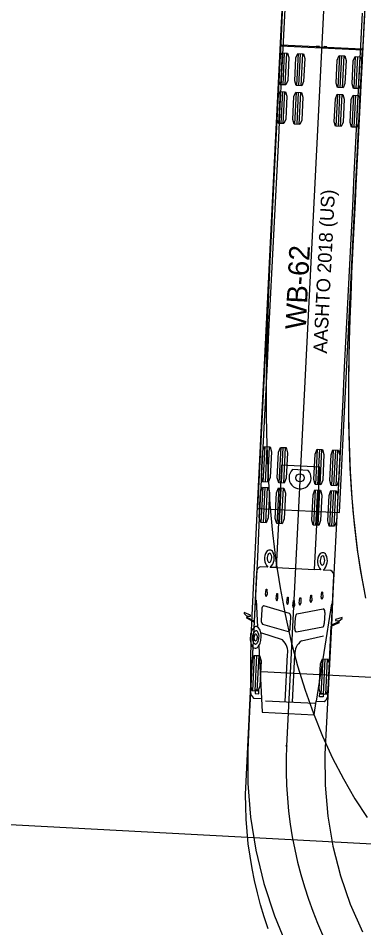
# Model space of a CAD drawing. Extents: x 260275 to 261282, y 610916 to 614143.
# Drawn here: x 260983.2 to 261018.9, y 611607.9 to 611701.9 of the extents above; entities that cross this region are included whole.
import ezdxf

# ---------------------------------------------------------------- set-up
doc = ezdxf.new("R2010")
doc.units = 0
doc.layers.add('DR_P_Ditch', color=7, linetype='Continuous')
doc.layers.add('UT_X_Water_Cells', color=7, linetype='Continuous')

msp = doc.modelspace()

# ---------------------------------------------------------------- linework, layer by layer
at = {"layer": 'DR_P_Ditch'}
msp.add_line((260830.144, 611626.697), (261021.455, 611616.54), dxfattribs=at)
at = {"layer": 'UT_X_Water_Cells'}
for p, q in [((261031.95, 612045.486), (261010.925, 611626.741)), ((261010.3, 611699.055), (261018.79, 611698.629)), ((261010.328, 611695.04), (261010.494, 611698.335)), ((261010.557, 611695.028), (261010.722, 611698.324)), ((261010.786, 611695.017), (261010.951, 611698.312)), ((261011.976, 611694.957), (261012.142, 611698.253)), ((261012.205, 611694.945), (261012.37, 611698.241)), ((261012.434, 611694.934), (261012.599, 611698.23)), ((261014.018, 611698.939), (261014.283, 611698.925)), ((261014.808, 611698.899), (261014.285, 611698.925)), ((261014.548, 611698.912), (261014.545, 611698.842)), ((261014.814, 611698.899), (261015.079, 611698.886)), ((261016.254, 611694.742), (261016.419, 611698.038)), ((261016.483, 611694.73), (261016.648, 611698.026)), ((261016.712, 611694.719), (261016.877, 611698.015)), ((261017.902, 611694.659), (261018.067, 611697.955)), ((261018.131, 611694.648), (261018.296, 611697.944)), ((261018.36, 611694.636), (261018.525, 611697.932)), ((261010.128, 611691.045), (261010.293, 611694.34)), ((261010.356, 611691.033), (261010.522, 611694.329)), ((261010.585, 611691.022), (261010.751, 611694.317)), ((261011.775, 611690.962), (261011.941, 611694.258)), ((261012.004, 611690.95), (261012.17, 611694.246)), ((261012.233, 611690.939), (261012.399, 611694.235)), ((261016.053, 611690.747), (261016.219, 611694.043)), ((261016.282, 611690.736), (261016.448, 611694.031)), ((261016.511, 611690.724), (261016.677, 611694.02)), ((261017.701, 611690.664), (261017.867, 611693.96)), ((261017.93, 611690.653), (261018.096, 611693.949)), ((261018.159, 611690.641), (261018.325, 611693.937)), ((261008.518, 611653.995), (261008.701, 611657.657)), ((261008.746, 611653.984), (261008.93, 611657.646)), ((261008.975, 611653.972), (261009.159, 611657.634)), ((261010.165, 611653.913), (261010.349, 611657.575)), ((261010.394, 611653.901), (261010.578, 611657.563)), ((261010.623, 611653.89), (261010.807, 611657.552)), ((261013.944, 611653.723), (261014.128, 611657.385)), ((261014.173, 611653.711), (261014.357, 611657.373)), ((261014.402, 611653.7), (261014.586, 611657.362)), ((261015.592, 611653.64), (261015.776, 611657.302)), ((261015.821, 611653.629), (261016.005, 611657.291)), ((261016.05, 611653.617), (261016.234, 611657.279)), ((261013.162, 611655.194), (261011.548, 611655.275)), ((261008.307, 611649.801), (261008.491, 611653.463)), ((261008.536, 611649.789), (261008.72, 611653.451)), ((261008.765, 611649.778), (261008.949, 611653.44)), ((261009.955, 611649.718), (261010.139, 611653.38)), ((261010.184, 611649.706), (261010.368, 611653.368)), ((261010.413, 611649.695), (261010.596, 611653.357)), ((261013.733, 611649.528), (261013.917, 611653.19)), ((261013.962, 611649.517), (261014.146, 611653.179)), ((261014.191, 611649.505), (261014.375, 611653.167)), ((261015.381, 611649.445), (261015.565, 611653.107)), ((261015.61, 611649.434), (261015.794, 611653.096)), ((261015.839, 611649.422), (261016.023, 611653.084)), ((261008.973, 611645.195), (261008.199, 611645.234)), ((261009.86, 611645.15), (261013.828, 611644.951)), ((261015.489, 611644.868), (261014.715, 611644.906)), ((261008.746, 611642.38), (261008.81, 611642.927)), ((261008.81, 611642.927), (261008.892, 611642.923)), ((261008.892, 611642.923), (261008.9, 611642.372)), ((261014.504, 611642.091), (261014.568, 611642.638)), ((261014.568, 611642.638), (261014.65, 611642.634)), ((261014.65, 611642.634), (261014.659, 611642.083)), ((261007.776, 611641.812), (261007.929, 611639.012)), ((261009.843, 611641.938), (261009.906, 611642.486)), ((261009.906, 611642.486), (261009.989, 611642.481)), ((261009.989, 611642.481), (261009.997, 611641.931)), ((261010.942, 611641.549), (261011.005, 611642.096)), ((261011.005, 611642.096), (261011.088, 611642.092)), ((261011.088, 611642.092), (261011.096, 611641.541)), ((261011.574, 611641.208), (261011.637, 611641.755)), ((261011.637, 611641.755), (261011.72, 611641.751)), ((261011.72, 611641.751), (261011.728, 611641.2)), ((261012.237, 611641.484), (261012.3, 611642.031)), ((261012.3, 611642.031), (261012.383, 611642.027)), ((261012.383, 611642.027), (261012.391, 611641.476)), ((261013.369, 611641.736), (261013.433, 611642.309)), ((261013.433, 611642.309), (261013.515, 611642.304)), ((261013.515, 611642.304), (261013.523, 611641.729)), ((261008.363, 611640.83), (261008.306, 611639.7)), ((261011.221, 611640.412), (261008.563, 611641.19)), ((261011.999, 611640.372), (261014.722, 611640.881)), ((261015.567, 611641.42), (261013.995, 611631.352)), ((261006.831, 611640.13), (261006.811, 611640.147)), ((261006.857, 611640.13), (261006.831, 611640.13)), ((261011.297, 611638.905), (261011.354, 611640.034)), ((261011.772, 611638.881), (261011.829, 611640.01)), ((261014.885, 611640.502), (261014.828, 611639.373)), ((261008.439, 611639.323), (261011.097, 611638.544)), ((261014.658, 611639.011), (261011.935, 611638.502)), ((261016.313, 611639.655), (261016.339, 611639.652)), ((261016.339, 611639.652), (261016.36, 611639.668)), ((261010.491, 611637.681), (261008.25, 611638.431)), ((261012.452, 611637.583), (261014.745, 611638.102)), ((261008.036, 611637.05), (261008.332, 611631.636)), ((261007.432, 611636.947), (261007.196, 611632.252)), ((261007.434, 611632.423), (261007.618, 611636.085)), ((261007.663, 611632.411), (261007.847, 611636.073)), ((261007.892, 611632.4), (261008.076, 611636.062)), ((261010.77, 611631.288), (261011.015, 611636.174)), ((261011.534, 611631.25), (261011.78, 611636.135)), ((261014.509, 611632.067), (261014.693, 611635.729)), ((261014.738, 611632.056), (261014.922, 611635.718)), ((261014.967, 611632.044), (261015.15, 611635.706)), ((261050.252, 611632.276), (261008.305, 611634.382)), ((261007.685, 611632.506), (261007.667, 611632.15)), ((261008.063, 611632.487), (261007.685, 611632.506)), ((261008.045, 611632.131), (261008.063, 611632.487)), ((261007.667, 611632.15), (261008.045, 611632.131)), ((261008.735, 611631.391), (261013.834, 611631.135)), ((261014.329, 611631.816), (261014.347, 611632.171)), ((261014.707, 611631.797), (261014.329, 611631.816)), ((261014.347, 611632.171), (261014.725, 611632.152)), ((261014.725, 611632.152), (261014.707, 611631.797)), ((261008.41, 611630.204), (261013.774, 611629.935))]:
    msp.add_line(p, q, dxfattribs=at)
for points in [[(261009.03, 611607.833), (261008.614, 611609.074), (261008.239, 611610.317), (261007.904, 611611.564), (261007.612, 611612.816), (261007.354, 611614.07), (261007.139, 611615.334), (261006.964, 611616.606), (261006.83, 611617.886), (261006.739, 611619.173), (261006.692, 611620.467), (261006.69, 611621.766), (261006.735, 611623.071), (261007.238, 611633.079), (261007.231, 611635.458), (261007.275, 611637.841), (261007.358, 611640.225), (261009.34, 611680.102), (261030.965, 612110.617)], [(261039.447, 612110.045), (261018.12, 611685.301), (261017.62, 611674.839), (261017.432, 611669.765), (261017.367, 611667.279), (261017.327, 611664.831), (261017.315, 611662.421), (261017.334, 611660.053), (261017.389, 611657.727), (261017.481, 611655.445), (261017.613, 611653.21), (261017.787, 611651.022), (261018.005, 611648.883), (261018.268, 611646.796), (261018.578, 611644.761), (261018.933, 611642.78)], [(261010.74, 611702.835), (261010.573, 611699.507), (261010.406, 611696.178), (261010.239, 611692.849), (261010.072, 611689.521), (261009.905, 611686.192), (261009.738, 611682.863), (261009.57, 611679.535), (261009.403, 611676.206), (261009.236, 611672.877), (261009.069, 611669.549), (261008.902, 611666.22), (261008.735, 611662.891), (261008.568, 611659.563), (261008.4, 611656.234), (261008.233, 611652.905), (261008.066, 611649.577), (261007.899, 611646.248), (261007.732, 611642.92), (261007.565, 611639.591), (261007.398, 611636.262), (261007.231, 611632.934), (261007.063, 611629.605), (261006.901, 611626.262), (261006.918, 611622.836), (261007.202, 611619.39), (261007.755, 611615.949), (261008.575, 611612.539), (261009.659, 611609.184), (261011.002, 611605.908)], [(261010.516, 611703.356), (261010.349, 611700.027), (261010.182, 611696.699), (261010.015, 611693.37), (261009.848, 611690.041), (261009.681, 611686.714), (261009.514, 611683.394), (261009.352, 611680.087), (261009.198, 611676.801), (261009.06, 611673.54), (261008.945, 611670.307), (261008.862, 611667.105), (261008.819, 611663.938), (261008.824, 611660.809), (261008.885, 611657.721), (261009.008, 611654.679), (261009.201, 611651.687), (261009.469, 611648.748), (261009.816, 611645.868), (261010.246, 611643.051), (261010.761, 611640.301), (261011.364, 611637.623), (261012.055, 611635.022), (261012.834, 611632.502), (261013.7, 611630.069), (261014.652, 611627.726), (261015.688, 611625.478), (261016.804, 611623.329), (261017.997, 611621.282), (261019.262, 611619.342)], [(261019.006, 611702.93), (261018.838, 611699.601), (261018.671, 611696.272), (261018.504, 611692.944), (261018.337, 611689.615), (261018.17, 611686.287), (261018.004, 611682.97), (261017.842, 611679.676), (261017.689, 611676.418), (261017.553, 611673.203), (261017.441, 611670.038), (261017.36, 611666.928), (261017.318, 611663.877), (261017.323, 611660.888), (261017.381, 611657.966), (261017.497, 611655.112), (261017.677, 611652.332), (261017.923, 611649.627), (261018.24, 611647.002), (261018.628, 611644.458), (261019.089, 611642)], [(261018.73, 611702.434), (261018.563, 611699.105), (261018.396, 611695.777), (261018.229, 611692.448), (261018.062, 611689.119), (261017.895, 611685.791), (261017.728, 611682.462), (261017.56, 611679.134), (261017.393, 611675.805), (261017.226, 611672.476), (261017.059, 611669.148), (261016.892, 611665.819), (261016.725, 611662.49), (261016.558, 611659.162), (261016.39, 611655.833), (261016.223, 611652.504), (261016.056, 611649.176), (261015.889, 611645.847), (261015.722, 611642.518), (261015.555, 611639.19), (261015.388, 611635.861), (261015.22, 611632.532), (261015.053, 611629.204), (261014.892, 611625.891), (261014.911, 611622.665), (261015.187, 611619.485), (261015.717, 611616.365), (261016.496, 611613.322), (261017.517, 611610.37), (261018.77, 611607.525)], [(261010.326, 611699.124), (261010.304, 611699.125), (261007.9, 611651.256), (261012.145, 611651.043), (261016.39, 611650.83), (261018.793, 611698.699), (261018.771, 611698.7)], [(261014.289, 611698.996), (261014.023, 611699.009), (261014.021, 611699.009), (261014.018, 611698.939), (261013.982, 611698.941), (261010.351, 611699.123), (261010.35, 611699.123)], [(261018.747, 611698.702), (261018.746, 611698.701), (261015.115, 611698.884), (261015.079, 611698.886), (261015.083, 611698.956), (261015.081, 611698.956), (261014.815, 611698.969)], [(261014.458, 611644.919), (261013.828, 611644.951), (261014.36, 611655.538), (261010.391, 611655.737), (261009.86, 611645.15), (261009.23, 611645.182)], [(261007.821, 611644.694), (261007.566, 611639.619), (261006.863, 611640.01), (261006.863, 611640.011)], [(261016.295, 611639.537), (261016.295, 611639.537), (261015.556, 611639.218), (261015.811, 611644.293)], [(261006.853, 611640.048), (261006.857, 611640.13), (261007.178, 611640.13), (261007.183, 611640.233), (261006.535, 611640.523), (261006.529, 611640.403), (261006.811, 611640.147), (261006.808, 611640.06)], [(261006.842, 611639.925), (261007.561, 611639.519), (261007.532, 611638.947)], [(261016.355, 611639.581), (261016.36, 611639.668), (261016.667, 611639.894), (261016.673, 611640.014), (261015.999, 611639.79), (261015.994, 611639.687), (261016.313, 611639.655), (261016.308, 611639.573)], [(261015.186, 611631.851), (261015.551, 611639.118), (261016.308, 611639.45)], [(261007.518, 611631.677), (261008.332, 611631.636), (261008.409, 611630.216)], [(261008.41, 611630.204), (261013.774, 611629.935), (261013.995, 611631.352), (261014.809, 611631.311)]]:
    msp.add_lwpolyline(points, dxfattribs=at)
for points in [[(261010.843, 611695.014), (261010.271, 611695.042), (261010.122, 611695.512), (261010.242, 611697.885), (261010.437, 611698.338), (261011.008, 611698.31), (261011.157, 611697.839), (261011.038, 611695.466)], [(261012.491, 611694.931), (261011.919, 611694.96), (261011.77, 611695.43), (261011.889, 611697.803), (261012.085, 611698.255), (261012.656, 611698.227), (261012.805, 611697.757), (261012.686, 611695.384)], [(261016.769, 611694.716), (261016.197, 611694.745), (261016.048, 611695.215), (261016.167, 611697.588), (261016.363, 611698.041), (261016.934, 611698.012), (261017.083, 611697.542), (261016.964, 611695.169)], [(261018.416, 611694.633), (261017.845, 611694.662), (261017.696, 611695.132), (261017.815, 611697.505), (261018.011, 611697.958), (261018.582, 611697.929), (261018.731, 611697.459), (261018.612, 611695.086)], [(261010.642, 611691.019), (261010.071, 611691.047), (261009.922, 611691.517), (261010.041, 611693.89), (261010.236, 611694.343), (261010.808, 611694.315), (261010.956, 611693.845), (261010.837, 611691.472)], [(261012.29, 611690.936), (261011.719, 611690.965), (261011.57, 611691.435), (261011.689, 611693.808), (261011.884, 611694.261), (261012.455, 611694.232), (261012.604, 611693.762), (261012.485, 611691.389)], [(261016.568, 611690.721), (261015.997, 611690.75), (261015.848, 611691.22), (261015.967, 611693.593), (261016.162, 611694.046), (261016.733, 611694.017), (261016.882, 611693.547), (261016.763, 611691.174)], [(261018.216, 611690.638), (261017.645, 611690.667), (261017.496, 611691.137), (261017.615, 611693.51), (261017.81, 611693.963), (261018.381, 611693.934), (261018.53, 611693.464), (261018.411, 611691.091)], [(261009.032, 611653.97), (261008.461, 611653.998), (261008.314, 611654.52), (261008.447, 611657.156), (261008.645, 611657.66), (261009.216, 611657.632), (261009.362, 611657.11), (261009.23, 611654.474)], [(261010.68, 611653.887), (261010.109, 611653.915), (261009.962, 611654.437), (261010.095, 611657.073), (261010.293, 611657.578), (261010.864, 611657.549), (261011.01, 611657.027), (261010.878, 611654.391)], [(261014.459, 611653.697), (261013.887, 611653.726), (261013.741, 611654.247), (261013.873, 611656.884), (261014.071, 611657.388), (261014.642, 611657.359), (261014.789, 611656.838), (261014.656, 611654.201)], [(261016.106, 611653.614), (261015.535, 611653.643), (261015.389, 611654.164), (261015.521, 611656.801), (261015.719, 611657.305), (261016.29, 611657.276), (261016.437, 611656.755), (261016.304, 611654.118)], [(261008.821, 611649.775), (261008.25, 611649.803), (261008.104, 611650.325), (261008.236, 611652.961), (261008.434, 611653.466), (261009.005, 611653.437), (261009.152, 611652.916), (261009.019, 611650.279)], [(261010.469, 611649.692), (261009.898, 611649.721), (261009.752, 611650.242), (261009.884, 611652.879), (261010.082, 611653.383), (261010.653, 611653.354), (261010.8, 611652.833), (261010.667, 611650.196)], [(261014.248, 611649.502), (261013.677, 611649.531), (261013.53, 611650.052), (261013.663, 611652.689), (261013.861, 611653.193), (261014.432, 611653.164), (261014.578, 611652.643), (261014.446, 611650.006)], [(261015.896, 611649.42), (261015.325, 611649.448), (261015.178, 611649.97), (261015.311, 611652.606), (261015.508, 611653.11), (261016.08, 611653.082), (261016.226, 611652.56), (261016.094, 611649.924)], [(261007.949, 611632.397), (261007.378, 611632.425), (261007.231, 611632.947), (261007.364, 611635.583), (261007.561, 611636.087), (261008.133, 611636.059), (261008.279, 611635.537), (261008.147, 611632.901)], [(261015.023, 611632.041), (261014.452, 611632.07), (261014.306, 611632.591), (261014.438, 611635.228), (261014.636, 611635.732), (261015.207, 611635.704), (261015.354, 611635.182), (261015.221, 611632.546)]]:
    msp.add_lwpolyline(points, close=True, dxfattribs=at)
for centre, radius in [((261010.34, 611699.158), 0.0266), ((261018.761, 611698.735), 0.0266), ((261012.315, 611654.427), 0.424), ((261010.925, 611626.741), 0.0417), ((261010.925, 611626.741), 0.0417)]:
    msp.add_circle(centre, radius, dxfattribs=at)
for centre, radius, start, end in [((261010.34, 611699.158), 0.0363, 286.88607, 248.0487), ((261014.287, 611698.961), 0.0354, 91.41704, 263.6025), ((261014.287, 611698.961), 0.0352, 266.52344, 87.10992), ((261014.813, 611698.934), 0.0352, 87.14108, 267.72757), ((261014.814, 611698.934), 0.0352, 266.91304, 89.55244), ((261018.761, 611698.735), 0.0363, 286.20231, 247.36494), ((261012.315, 611654.427), 1.143, 132.1255, 42.1255), ((261009.986, 611646.078), 1.344, 147.53526, 221.09006), ((261009.172, 611646.589), 0.383, 27.59628, 146.65472), ((261009.774, 611646.128), 0.86, 155.59014, 195.55953), ((261009.205, 611646.405), 0.228, 97.92836, 159.8232), ((261009.099, 611646.38), 0.262, 6.80834, 73.33353), ((261008.311, 611646.162), 1.344, 313.16094, 26.71574), ((261008.507, 611646.194), 0.879, 339.66236, 14.25761), ((261015.471, 611645.802), 1.344, 147.53526, 221.09006), ((261014.656, 611646.305), 0.387, 28.62104, 145.62996), ((261013.796, 611645.886), 1.344, 313.16094, 26.71574), ((261009.228, 611645.965), 0.29, 193.32121, 249.48124), ((261009.089, 611645.937), 0.247, 278.8428, 348.7219), ((261015.279, 611645.854), 0.879, 159.9934, 194.58864), ((261014.674, 611645.657), 0.247, 185.52911, 255.4082), ((261014.708, 611646.098), 0.262, 100.91747, 167.44267), ((261014.538, 611645.698), 0.29, 284.76976, 340.92979), ((261014.605, 611646.134), 0.228, 14.4278, 76.32264), ((261014.011, 611645.916), 0.86, 338.69148, 18.66086), ((261008.392, 611644.696), 0.571, 109.81853, 180.21012), ((261015.243, 611644.352), 0.571, 354.04089, 64.43248), ((261008.932, 611642.329), 0.192, 164.57524, 232.04981), ((261008.711, 611642.34), 0.192, 302.17384, 9.70311), ((261010.028, 611641.887), 0.192, 164.57524, 232.04981), ((261009.808, 611641.898), 0.192, 302.17384, 9.70311), ((261013.554, 611641.71), 0.192, 164.5479, 232.07716), ((261013.334, 611641.721), 0.192, 302.20119, 9.67576), ((261014.69, 611642.039), 0.192, 164.5479, 232.07716), ((261014.469, 611642.051), 0.192, 302.20119, 9.67576), ((261008.695, 611640.884), 0.334, 113.39037, 185.98833), ((261011.127, 611641.497), 0.192, 164.57524, 232.04981), ((261010.907, 611641.508), 0.192, 302.17384, 9.70311), ((261011.759, 611641.157), 0.192, 164.57524, 232.04981), ((261011.538, 611641.168), 0.192, 302.20119, 9.67576), ((261012.422, 611641.432), 0.192, 164.5479, 232.07716), ((261012.201, 611641.444), 0.192, 302.20119, 9.67576), ((261014.56, 611640.59), 0.334, 348.26267, 60.86063), ((261006.912, 611639.987), 0.127, 145.02093, 209.23008), ((261006.821, 611639.939), 0.0244, 212.94354, 326.25791), ((261006.753, 611640.003), 0.11, 4.06966, 24.17798), ((261010.963, 611640.11), 0.397, 351.20134, 49.36435), ((261012.226, 611640.047), 0.397, 124.88665, 183.04966), ((261008.151, 611638.261), 0.924, 132.02262, 168.30076), ((261007.767, 611638.759), 0.301, 57.35677, 141.25506), ((261007.44, 611638.381), 0.799, 12.92493, 52.19257), ((261008.703, 611639.628), 0.403, 169.66784, 229.12579), ((261010.956, 611638.852), 0.342, 295.59721, 5.52369), ((261014.426, 611639.341), 0.403, 305.12521, 4.58316), ((261016.404, 611639.518), 0.11, 150.07302, 170.18134), ((261016.329, 611639.461), 0.0244, 207.99309, 321.30746), ((261016.244, 611639.519), 0.127, 325.02093, 29.23008), ((261009.368, 611637.852), 2.204, 164.32456, 183.95974), ((261008.617, 611637.886), 1.234, 176.75519, 194.33734), ((261008.298, 611637.967), 0.913, 140.43513, 180.69541), ((261008.181, 611637.91), 0.631, 150.93378, 193.73431), ((261007.75, 611638.425), 0.199, 40.92879, 141.5681), ((261007.74, 611638.171), 0.12, 12.10162, 157.57965), ((261007.288, 611637.959), 0.617, 349.4131, 22.60389), ((261007.161, 611638.017), 0.914, 353.95993, 36.01791), ((261006.279, 611638.024), 2.012, 356.76687, 15.44978), ((261012.107, 611638.794), 0.342, 168.72731, 238.65379), ((261008.897, 611637.806), 1.731, 183.5106, 198.70836), ((261007.95, 611637.445), 0.719, 195.6559, 223.91288), ((261007.824, 611637.639), 0.407, 188.35614, 251.16055), ((261007.785, 611637.792), 0.22, 188.13535, 249.83363), ((261007.683, 611637.521), 0.268, 272.19814, 335.87577), ((261007.625, 611637.841), 0.27, 288.27444, 1.01824), ((261006.972, 611637.954), 1.098, 330.39127, 358.28386), ((261007.158, 611637.669), 1.074, 318.58211, 342.85096), ((261006.24, 611638.002), 2.049, 341.50654, 357.43184), ((261009.41, 611636.461), 1.631, 349.85894, 48.44967), ((261013.406, 611636.26), 1.631, 125.80134, 184.39207), ((261007.693, 611637.145), 0.328, 217.21385, 266.11819), ((261007.668, 611637.198), 0.38, 270.45588, 320.97941), ((261007.985, 611632.316), 0.792, 184.65895, 233.81442), ((261014.408, 611631.994), 0.792, 300.43659, 349.59206), ((261052.872, 611624.635), 42, 177.1255, 293.79918)]:
    msp.add_arc(centre, radius, start, end, dxfattribs=at)
for centre, major_axis, start_param, end_param in [((261006.824, 611639.992), (-0.0039, -0.0781), 2.398717, 3.668019), ((261006.824, 611639.992), (0.0039, 0.0781), 3.71124, 4.981984), ((261016.332, 611639.514), (-0.0039, -0.0781), 4.442794, 5.713538), ((261016.332, 611639.514), (0.0039, 0.0781), 5.756759, 7.026061)]:
    msp.add_ellipse(centre, major_axis=major_axis, ratio=0.5, start_param=start_param, end_param=end_param, dxfattribs=at)

# ---------------------------------------------------------------- texts
for s, height, p in [('AASHTO 2018 (US)', 1.41667, (261015.093, 611667.25)), ('WB-62', 2.125, (261012.912, 611669.716))]:
    msp.add_text(s, height=height, rotation=87.1255, dxfattribs=at).set_placement(p)

doc.saveas('drawing.dxf')
